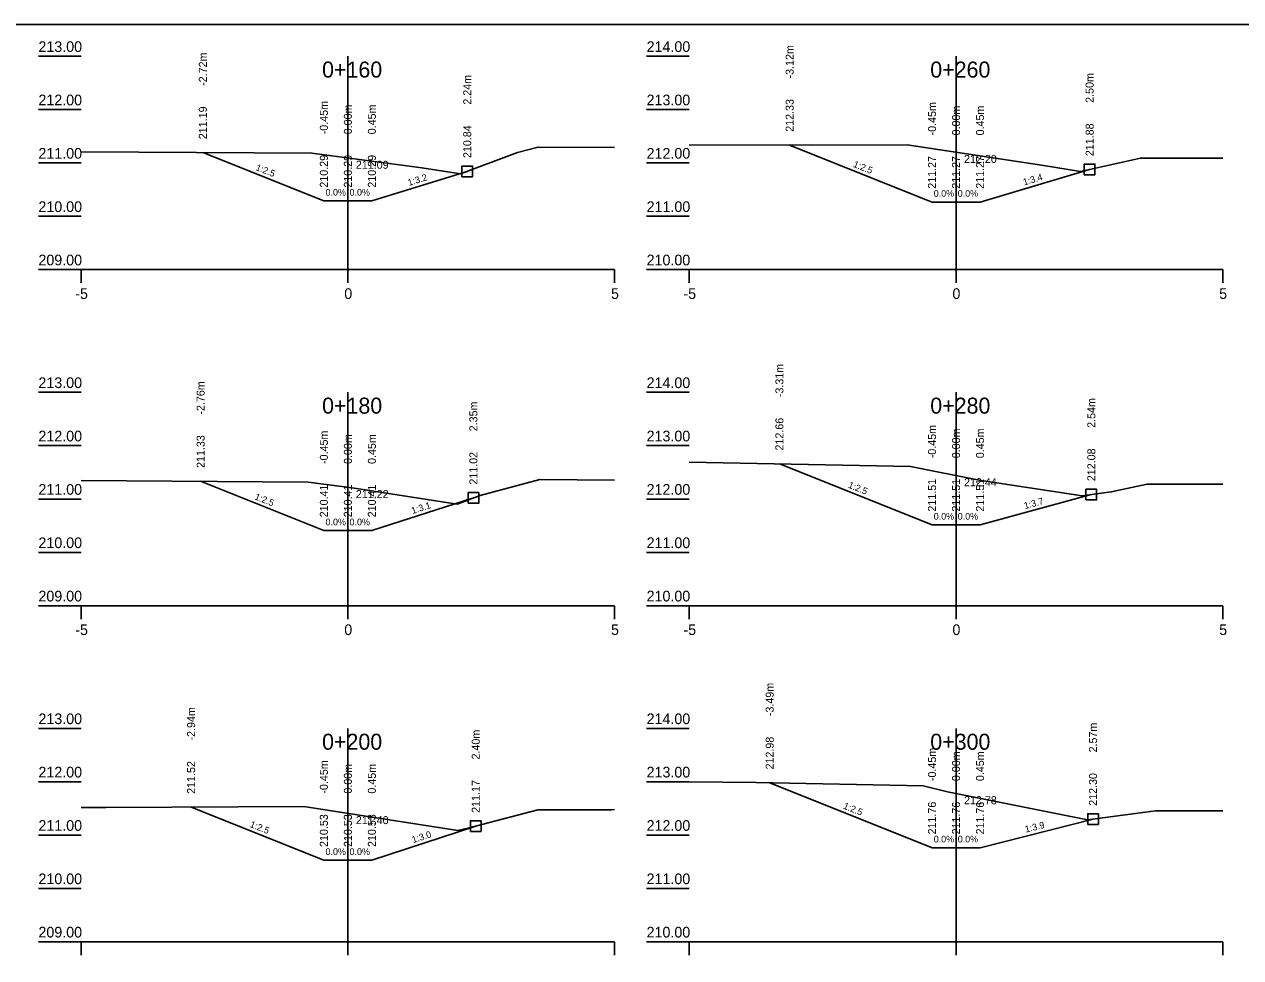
# Model space of a CAD drawing. Extents: x -577315 to -577212, y -1159820 to -1159790.
# Drawn here: x -577290.21 to -577267.41, y -1159807.85 to -1159790.35 of the extents above; entities that cross this region are included whole.
import ezdxf

# ---------------------------------------------------------------- set-up
doc = ezdxf.new("R2010")
doc.units = 0
for name, color, linetype in [('16', 7, 'Continuous'), ('21', 7, 'Continuous'), ('28', 7, 'Continuous'), ('59', 7, 'Continuous'), ('Body pricny rez', 7, 'Continuous'), ('Hranice_pozemku', 7, 'Continuous'), ('Popis pricneho profilu', 7, 'Continuous'), ('Rámy', 7, 'Continuous')]:
    doc.layers.add(name, color=color, linetype=linetype)

msp = doc.modelspace()

# ---------------------------------------------------------------- linework, layer by layer
for points in [[(-577289.143, -1159792.738), (-577284.816, -1159792.768), (-577282.757, -1159793.043), (-577282.033, -1159793.155), (-577280.962, -1159792.755), (-577280.576, -1159792.653), (-577279.143, -1159792.662)], [(-577277.743, -1159792.619), (-577273.659, -1159792.61), (-577271.138, -1159792.993), (-577270.407, -1159793.11), (-577269.507, -1159792.909), (-577269.286, -1159792.859), (-577267.743, -1159792.86)], [(-577273.193, -1159793.683), (-577275.862, -1159792.615)], [(-577284.593, -1159793.662), (-577286.861, -1159792.754)], [(-577283.693, -1159793.662), (-577281.905, -1159793.107)], [(-577272.293, -1159793.683), (-577270.239, -1159793.072)], [(-577284.593, -1159793.662), (-577284.143, -1159793.662), (-577283.693, -1159793.662)], [(-577273.193, -1159793.683), (-577272.743, -1159793.683), (-577272.293, -1159793.683)], [(-577277.743, -1159798.557), (-577273.598, -1159798.639), (-577272.309, -1159798.895), (-577270.38, -1159799.187), (-577269.834, -1159799.116), (-577269.163, -1159798.968), (-577267.743, -1159798.971)], [(-577273.193, -1159799.735), (-577276.054, -1159798.59)], [(-577289.143, -1159798.902), (-577284.89, -1159798.931), (-577284.06, -1159799.042), (-577282.096, -1159799.344), (-577281.66, -1159799.182), (-577280.542, -1159798.885), (-577279.143, -1159798.894)], [(-577284.593, -1159799.842), (-577286.903, -1159798.917)], [(-577283.693, -1159799.842), (-577281.79, -1159799.23)], [(-577272.293, -1159799.735), (-577270.207, -1159799.165)], [(-577273.193, -1159799.735), (-577272.743, -1159799.735), (-577272.293, -1159799.735)], [(-577284.593, -1159799.842), (-577284.143, -1159799.842), (-577283.693, -1159799.842)], [(-577277.743, -1159804.551), (-577276.491, -1159804.564), (-577273.358, -1159804.629), (-577272.906, -1159804.738), (-577270.276, -1159805.263), (-577269.191, -1159805.122), (-577269.001, -1159805.092), (-577267.743, -1159805.095)], [(-577273.193, -1159805.787), (-577276.236, -1159804.569)], [(-577289.143, -1159805.031), (-577288.68, -1159805.035), (-577284.969, -1159805.015), (-577284.288, -1159805.122), (-577282.084, -1159805.463), (-577281.868, -1159805.415), (-577280.584, -1159805.074), (-577279.202, -1159805.073), (-577279.143, -1159805.072)], [(-577284.593, -1159806.022), (-577287.081, -1159805.026)], [(-577283.693, -1159806.022), (-577281.746, -1159805.382)], [(-577272.293, -1159805.787), (-577270.175, -1159805.25)], [(-577273.193, -1159805.787), (-577272.743, -1159805.787), (-577272.293, -1159805.787)], [(-577284.593, -1159806.022), (-577284.143, -1159806.022), (-577283.693, -1159806.022)]]:
    msp.add_lwpolyline(points)
at = {"layer": '16'}
for p, q in [((-577289.143, -1159794.949), (-577279.143, -1159794.949)), ((-577277.743, -1159794.949), (-577267.743, -1159794.949)), ((-577289.143, -1159801.249), (-577279.143, -1159801.249)), ((-577277.743, -1159801.249), (-577267.743, -1159801.249)), ((-577289.143, -1159807.549), (-577279.143, -1159807.549)), ((-577277.743, -1159807.549), (-577267.743, -1159807.549))]:
    msp.add_line(p, q, dxfattribs=at)
at = {"layer": '21'}
for p, q in [((-577289.943, -1159790.949), (-577289.143, -1159790.949)), ((-577278.543, -1159790.949), (-577277.743, -1159790.949)), ((-577289.943, -1159791.949), (-577289.143, -1159791.949)), ((-577278.543, -1159791.949), (-577277.743, -1159791.949)), ((-577289.943, -1159792.949), (-577289.143, -1159792.949)), ((-577278.543, -1159792.949), (-577277.743, -1159792.949)), ((-577289.943, -1159793.949), (-577289.143, -1159793.949)), ((-577278.543, -1159793.949), (-577277.743, -1159793.949)), ((-577289.943, -1159794.949), (-577289.143, -1159794.949)), ((-577278.543, -1159794.949), (-577277.743, -1159794.949)), ((-577289.943, -1159797.249), (-577289.143, -1159797.249)), ((-577278.543, -1159797.249), (-577277.743, -1159797.249)), ((-577289.943, -1159798.249), (-577289.143, -1159798.249)), ((-577278.543, -1159798.249), (-577277.743, -1159798.249)), ((-577289.943, -1159799.249), (-577289.143, -1159799.249)), ((-577278.543, -1159799.249), (-577277.743, -1159799.249)), ((-577289.943, -1159800.249), (-577289.143, -1159800.249)), ((-577278.543, -1159800.249), (-577277.743, -1159800.249)), ((-577289.943, -1159801.249), (-577289.143, -1159801.249)), ((-577278.543, -1159801.249), (-577277.743, -1159801.249)), ((-577289.943, -1159803.549), (-577289.143, -1159803.549)), ((-577278.543, -1159803.549), (-577277.743, -1159803.549)), ((-577289.943, -1159804.549), (-577289.143, -1159804.549)), ((-577278.543, -1159804.549), (-577277.743, -1159804.549)), ((-577289.943, -1159805.549), (-577289.143, -1159805.549)), ((-577278.543, -1159805.549), (-577277.743, -1159805.549)), ((-577289.943, -1159806.549), (-577289.143, -1159806.549)), ((-577278.543, -1159806.549), (-577277.743, -1159806.549)), ((-577289.943, -1159807.549), (-577289.143, -1159807.549)), ((-577278.543, -1159807.549), (-577277.743, -1159807.549))]:
    msp.add_line(p, q, dxfattribs=at)
at = {"layer": '28'}
for p, q in [((-577284.143, -1159790.949), (-577284.143, -1159794.949)), ((-577272.743, -1159790.949), (-577272.743, -1159794.949)), ((-577284.143, -1159797.249), (-577284.143, -1159801.249)), ((-577272.743, -1159797.249), (-577272.743, -1159801.249)), ((-577284.143, -1159803.549), (-577284.143, -1159807.549)), ((-577272.743, -1159803.549), (-577272.743, -1159807.549))]:
    msp.add_line(p, q, dxfattribs=at)
at = {"layer": '59'}
for p, q in [((-577289.143, -1159795.199), (-577289.143, -1159794.949)), ((-577284.143, -1159795.199), (-577284.143, -1159794.949)), ((-577279.143, -1159795.199), (-577279.143, -1159794.949)), ((-577277.743, -1159795.199), (-577277.743, -1159794.949)), ((-577272.743, -1159795.199), (-577272.743, -1159794.949)), ((-577267.743, -1159795.199), (-577267.743, -1159794.949)), ((-577289.143, -1159801.499), (-577289.143, -1159801.249)), ((-577284.143, -1159801.499), (-577284.143, -1159801.249)), ((-577279.143, -1159801.499), (-577279.143, -1159801.249)), ((-577277.743, -1159801.499), (-577277.743, -1159801.249)), ((-577272.743, -1159801.499), (-577272.743, -1159801.249)), ((-577267.743, -1159801.499), (-577267.743, -1159801.249)), ((-577289.143, -1159807.799), (-577289.143, -1159807.549)), ((-577284.143, -1159807.799), (-577284.143, -1159807.549)), ((-577279.143, -1159807.799), (-577279.143, -1159807.549)), ((-577277.743, -1159807.799), (-577277.743, -1159807.549)), ((-577272.743, -1159807.799), (-577272.743, -1159807.549)), ((-577267.743, -1159807.799), (-577267.743, -1159807.549))]:
    msp.add_line(p, q, dxfattribs=at)
at = {"layer": 'Hranice_pozemku'}
for points in [[(-577282.005, -1159793.207), (-577281.805, -1159793.207), (-577281.805, -1159793.007), (-577282.005, -1159793.007)], [(-577270.339, -1159793.172), (-577270.139, -1159793.172), (-577270.139, -1159792.972), (-577270.339, -1159792.972)], [(-577281.89, -1159799.33), (-577281.69, -1159799.33), (-577281.69, -1159799.13), (-577281.89, -1159799.13)], [(-577270.307, -1159799.265), (-577270.107, -1159799.265), (-577270.107, -1159799.065), (-577270.307, -1159799.065)], [(-577270.275, -1159805.35), (-577270.075, -1159805.35), (-577270.075, -1159805.15), (-577270.275, -1159805.15)], [(-577281.846, -1159805.482), (-577281.646, -1159805.482), (-577281.646, -1159805.282), (-577281.846, -1159805.282)]]:
    msp.add_lwpolyline(points, close=True, dxfattribs=at)
at = {"layer": 'Rámy'}
msp.add_lwpolyline([(-577315.23, -1159790.351), (-577212.353, -1159790.351), (-577212.353, -1159820.051), (-577315.23, -1159820.051)], close=True, dxfattribs=at)

# ---------------------------------------------------------------- texts
for s, height, p in [('0+160', 0.3, (-577284.626, -1159791.349)), ('0+260', 0.3, (-577273.226, -1159791.349)), ('+', 0.001, (-577284.143, -1159793.662)), ('+', 0.001, (-577272.743, -1159793.683)), ('0+180', 0.3, (-577284.626, -1159797.649)), ('0+280', 0.3, (-577273.226, -1159797.649)), ('+', 0.001, (-577272.743, -1159799.735)), ('+', 0.001, (-577284.143, -1159799.842)), ('0+200', 0.3, (-577284.626, -1159803.949)), ('0+300', 0.3, (-577273.226, -1159803.949)), ('+', 0.001, (-577272.743, -1159805.787)), ('+', 0.001, (-577284.143, -1159806.022))]:
    msp.add_text(s, height=height).set_placement(p)
for s, rotation, p in [('1:2.5', 338.1986, (-577285.881, -1159793.079)), ('1:2.5', 338.1986, (-577274.681, -1159793.02)), ('1:3.2', 17.247, (-577282.998, -1159793.381)), ('1:3.4', 16.5584, (-577271.466, -1159793.372)), ('1:2.5', 338.1986, (-577274.777, -1159799.033)), ('1:2.5', 338.1986, (-577285.902, -1159799.251)), ('1:3.7', 15.2854, (-577271.45, -1159799.439)), ('1:3.1', 17.8127, (-577282.93, -1159799.531)), ('1:2.5', 338.1986, (-577274.868, -1159805.049)), ('1:2.5', 338.1986, (-577285.99, -1159805.395)), ('1:3.9', 14.2131, (-577271.434, -1159805.504)), ('1:3.0', 18.181, (-577282.919, -1159805.702))]:
    msp.add_text(s, height=0.125, rotation=rotation).set_placement(p)
at = {"layer": '16'}
for p in [(-577284.561, -1159793.562), (-577284.111, -1159793.562), (-577273.161, -1159793.583), (-577272.711, -1159793.583), (-577273.161, -1159799.635), (-577272.711, -1159799.635), (-577284.561, -1159799.742), (-577284.111, -1159799.742), (-577273.161, -1159805.687), (-577272.711, -1159805.687), (-577284.561, -1159805.922), (-577284.111, -1159805.922)]:
    msp.add_text('0.0%', height=0.125, rotation=360, dxfattribs=at).set_placement(p)
at = {"layer": '21'}
for s, p in [('213.00', (-577289.943, -1159790.869)), ('214.00', (-577278.543, -1159790.869)), ('212.00', (-577289.943, -1159791.869)), ('213.00', (-577278.543, -1159791.869)), ('211.00', (-577289.943, -1159792.869)), ('212.00', (-577278.543, -1159792.869)), ('210.00', (-577289.943, -1159793.869)), ('211.00', (-577278.543, -1159793.869)), ('209.00', (-577289.943, -1159794.869)), ('210.00', (-577278.543, -1159794.869)), ('-5', (-577289.253, -1159795.499)), ('0', (-577284.21, -1159795.499)), ('5', (-577279.21, -1159795.499)), ('-5', (-577277.853, -1159795.499)), ('0', (-577272.81, -1159795.499)), ('5', (-577267.81, -1159795.499)), ('213.00', (-577289.943, -1159797.169)), ('214.00', (-577278.543, -1159797.169)), ('212.00', (-577289.943, -1159798.169)), ('213.00', (-577278.543, -1159798.169)), ('211.00', (-577289.943, -1159799.169)), ('212.00', (-577278.543, -1159799.169)), ('210.00', (-577289.943, -1159800.169)), ('211.00', (-577278.543, -1159800.169)), ('209.00', (-577289.943, -1159801.169)), ('210.00', (-577278.543, -1159801.169)), ('-5', (-577289.253, -1159801.799)), ('0', (-577284.21, -1159801.799)), ('5', (-577279.21, -1159801.799)), ('-5', (-577277.853, -1159801.799)), ('0', (-577272.81, -1159801.799)), ('5', (-577267.81, -1159801.799)), ('213.00', (-577289.943, -1159803.469)), ('214.00', (-577278.543, -1159803.469)), ('212.00', (-577289.943, -1159804.469)), ('213.00', (-577278.543, -1159804.469)), ('211.00', (-577289.943, -1159805.469)), ('212.00', (-577278.543, -1159805.469)), ('210.00', (-577289.943, -1159806.469)), ('211.00', (-577278.543, -1159806.469)), ('209.00', (-577289.943, -1159807.469)), ('210.00', (-577278.543, -1159807.469))]:
    msp.add_text(s, height=0.2, dxfattribs=at).set_placement(p)
at = {"layer": '59'}
for s, p in [('211.09', (-577283.993, -1159793.058)), ('212.20', (-577272.593, -1159792.949)), ('212.44', (-577272.593, -1159799.009)), ('211.22', (-577283.993, -1159799.231)), ('212.78', (-577272.593, -1159804.97)), ('211.40', (-577283.993, -1159805.344))]:
    msp.add_text(s, height=0.15, dxfattribs=at).set_placement(p)
at = {"layer": 'Body pricny rez'}
for p in [(-577275.863, -1159792.615), (-577286.862, -1159792.755), (-577281.905, -1159793.107), (-577270.239, -1159793.073), (-577284.593, -1159793.662), (-577283.693, -1159793.662), (-577273.193, -1159793.683), (-577272.293, -1159793.683), (-577276.055, -1159798.591), (-577286.904, -1159798.918), (-577281.79, -1159799.231), (-577270.207, -1159799.165), (-577273.193, -1159799.735), (-577272.293, -1159799.735), (-577284.593, -1159799.842), (-577283.693, -1159799.842), (-577276.236, -1159804.57), (-577287.081, -1159805.027), (-577281.746, -1159805.383), (-577270.176, -1159805.251), (-577273.193, -1159805.787), (-577272.293, -1159805.787), (-577284.593, -1159806.022), (-577283.693, -1159806.022)]:
    msp.add_text('+', height=0.001, dxfattribs=at).set_placement(p)
at = {"layer": 'Popis pricneho profilu'}
for s, p in [('-3.12m', (-577275.787, -1159791.365)), ('-2.72m', (-577286.786, -1159791.504)), ('2.50m', (-577270.164, -1159791.822)), ('2.50m', (-577270.164, -1159791.822)), ('2.50m', (-577270.164, -1159791.822)), ('2.24m', (-577281.83, -1159791.857)), ('2.24m', (-577281.83, -1159791.857)), ('2.24m', (-577281.83, -1159791.857)), ('212.33', (-577275.787, -1159792.365)), ('211.19', (-577286.786, -1159792.504)), ('-0.45m', (-577284.518, -1159792.412)), ('0.00m', (-577284.068, -1159792.412)), ('0.45m', (-577283.618, -1159792.412)), ('-0.45m', (-577273.118, -1159792.433)), ('0.00m', (-577272.668, -1159792.433)), ('0.45m', (-577272.218, -1159792.433)), ('211.88', (-577270.164, -1159792.822)), ('210.84', (-577281.83, -1159792.857)), ('210.29', (-577284.518, -1159793.412)), ('210.29', (-577284.068, -1159793.412)), ('210.29', (-577283.618, -1159793.412)), ('211.27', (-577273.118, -1159793.433)), ('211.27', (-577272.668, -1159793.433)), ('211.27', (-577272.218, -1159793.433)), ('-3.31m', (-577275.979, -1159797.34)), ('-2.76m', (-577286.828, -1159797.667)), ('2.35m', (-577281.715, -1159797.98)), ('2.35m', (-577281.715, -1159797.98)), ('2.35m', (-577281.715, -1159797.98)), ('2.54m', (-577270.132, -1159797.915)), ('2.54m', (-577270.132, -1159797.915)), ('2.54m', (-577270.132, -1159797.915)), ('212.66', (-577275.979, -1159798.34)), ('-0.45m', (-577273.118, -1159798.485)), ('211.33', (-577286.828, -1159798.667)), ('-0.45m', (-577284.518, -1159798.592)), ('0.00m', (-577284.068, -1159798.592)), ('0.45m', (-577283.618, -1159798.592)), ('0.00m', (-577272.668, -1159798.485)), ('0.45m', (-577272.218, -1159798.485)), ('211.02', (-577281.715, -1159798.98)), ('212.08', (-577270.132, -1159798.915)), ('210.41', (-577284.518, -1159799.592)), ('210.41', (-577284.068, -1159799.592)), ('210.41', (-577283.618, -1159799.592)), ('211.51', (-577273.118, -1159799.485)), ('211.51', (-577272.668, -1159799.485)), ('211.51', (-577272.218, -1159799.485)), ('-3.49m', (-577276.161, -1159803.319)), ('-2.94m', (-577287.006, -1159803.776)), ('2.40m', (-577281.671, -1159804.132)), ('2.40m', (-577281.671, -1159804.132)), ('2.40m', (-577281.671, -1159804.132)), ('2.57m', (-577270.1, -1159804)), ('2.57m', (-577270.1, -1159804)), ('2.57m', (-577270.1, -1159804)), ('212.98', (-577276.161, -1159804.319)), ('-0.45m', (-577273.118, -1159804.537)), ('0.00m', (-577272.668, -1159804.537)), ('0.45m', (-577272.218, -1159804.537)), ('211.52', (-577287.006, -1159804.776)), ('-0.45m', (-577284.518, -1159804.772)), ('0.00m', (-577284.068, -1159804.772)), ('0.45m', (-577283.618, -1159804.772)), ('211.17', (-577281.671, -1159805.132)), ('212.30', (-577270.1, -1159805)), ('211.76', (-577273.118, -1159805.537)), ('211.76', (-577272.668, -1159805.537)), ('211.76', (-577272.218, -1159805.537)), ('210.53', (-577284.518, -1159805.772)), ('210.53', (-577284.068, -1159805.772)), ('210.53', (-577283.618, -1159805.772))]:
    msp.add_text(s, height=0.15, rotation=90, dxfattribs=at).set_placement(p)

doc.saveas('drawing.dxf')
